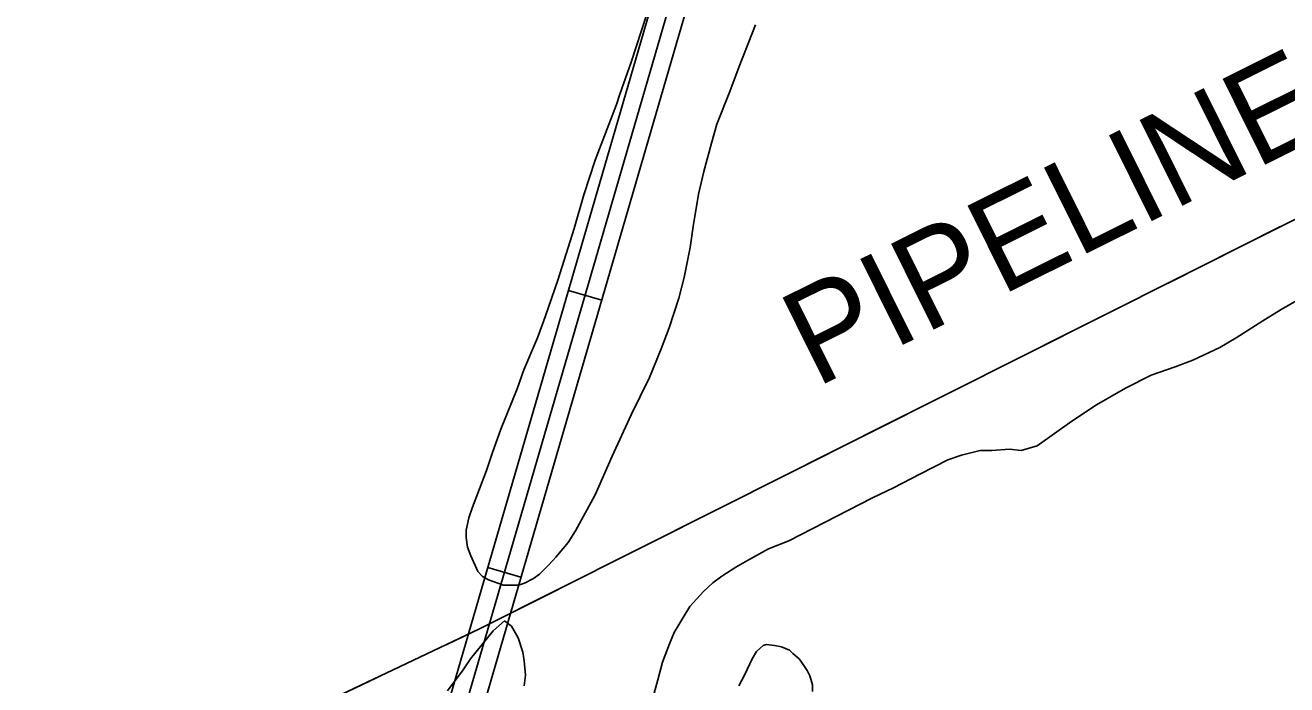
# Model space of a CAD drawing. Extents: x 3567028 to 3605064, y 510945 to 536587.
# Drawn here: x 3592975 to 3594068, y 517478 to 518049 of the extents above; entities that cross this region are included whole.
import ezdxf

# ---------------------------------------------------------------- set-up
doc = ezdxf.new("R2010")
doc.units = 0
for name, color, linetype in [('V-ROAD-CNTR', 7, 'Continuous'), ('V-SITE-VEGE', 7, 'Continuous'), ('V-UTIL-IDEN', 7, 'Continuous'), ('V-UTIL-LINE', 7, 'Continuous')]:
    doc.layers.add(name, color=color, linetype=linetype)

msp = doc.modelspace()

# ---------------------------------------------------------------- linework, layer by layer
at = {"layer": 'V-ROAD-CNTR'}
for p, q in [((3593446.1, 517819.3), (3593474.9, 517810.9)), ((3593376.1, 517579.3), (3593404.9, 517570.9))]:
    msp.add_line(p, q, dxfattribs=at)
for points in [[(3593075.5, 516536.6), (3593279.2, 517246.5), (3593647.5, 518510.8), (3593973.3, 519612.8), (3594189.4, 520289.5), (3594236.4, 520485.4), (3594284.3, 520636.9), (3594416.6, 521086), (3594537.9, 521497.5)], [(3594552.2, 521493.2), (3594431, 521081.8), (3594298.6, 520632.5), (3594250.9, 520481.3), (3594203.9, 520285.4), (3593987.6, 519608.4), (3593661.9, 518506.6), (3593293.6, 517242.3), (3593091.2, 516536.7)], [(3593106.8, 516536.8), (3593308, 517238.2), (3593676.3, 518502.4), (3594001.9, 519604), (3594218.3, 520281.4), (3594265.3, 520477.3), (3594313, 520628.1), (3594342.1, 520727.2)]]:
    msp.add_lwpolyline(points, dxfattribs=at)
at = {"layer": 'V-SITE-VEGE'}
for p, q in [((3594063.5, 517802.9), (3594085.2, 517815.2)), ((3594047.6, 517792.9), (3594063.5, 517802.9)), ((3594024.7, 517778.2), (3594047.6, 517792.9)), ((3593987, 517758.8), (3594010.5, 517770)), ((3594010.5, 517770), (3594024.7, 517778.2)), ((3593971.7, 517753), (3593987, 517758.8)), ((3593951.1, 517745.9), (3593971.7, 517753)), ((3593928.8, 517734.7), (3593951.1, 517745.9)), ((3593903.5, 517720.1), (3593928.8, 517734.7)), ((3593882.3, 517706), (3593903.5, 517720.1)), ((3593852.3, 517684.8), (3593882.3, 517706)), ((3593812.9, 517680.7), (3593828.2, 517681.9)), ((3593828.2, 517681.9), (3593838.2, 517680.7)), ((3593838.2, 517680.7), (3593852.3, 517684.8)), ((3593763, 517666.6), (3593774.7, 517672.5)), ((3593774.7, 517672.5), (3593786.5, 517676.6)), ((3593786.5, 517676.6), (3593802.9, 517680.7)), ((3593802.9, 517680.7), (3593812.9, 517680.7)), ((3593727.7, 517648.4), (3593750.6, 517660.1)), ((3593750.6, 517660.1), (3593763, 517666.6)), ((3593709.4, 517639.6), (3593727.7, 517648.4)), ((3593637.1, 517602.6), (3593709.4, 517639.6)), ((3593601.2, 517585.5), (3593619.5, 517595.5)), ((3593619.5, 517595.5), (3593637.1, 517602.6)), ((3593591.2, 517579.6), (3593601.2, 517585.5)), ((3593571.2, 517566.1), (3593578.9, 517572)), ((3593578.9, 517572), (3593591.2, 517579.6)), ((3593563, 517558.5), (3593571.2, 517566.1)), ((3593551.2, 517545.6), (3593563, 517558.5)), ((3593545.4, 517536.2), (3593551.2, 517545.6)), ((3593380.7, 517524.5), (3593390.7, 517533.3)), ((3593390.7, 517533.3), (3593396.6, 517528.6)), ((3593396.6, 517528.6), (3593402.5, 517518.6)), ((3593537.7, 517523.2), (3593545.4, 517536.2)), ((3593361.3, 517500.4), (3593380.7, 517524.5)), ((3593402.5, 517518.6), (3593406.6, 517506.2)), ((3593533.6, 517513.2), (3593537.7, 517523.2)), ((3593406.6, 517506.2), (3593407.8, 517498.6)), ((3593527.7, 517497.4), (3593533.6, 517513.2)), ((3593608.9, 517506.7), (3593605.3, 517500.3)), ((3593614.7, 517512), (3593608.9, 517506.7)), ((3593617.7, 517512.6), (3593614.7, 517512)), ((3593624.7, 517512), (3593617.7, 517512.6)), ((3593630.6, 517510.8), (3593624.7, 517512)), ((3593637.7, 517507.9), (3593630.6, 517510.8)), ((3593640.6, 517505), (3593637.7, 517507.9)), ((3593354.8, 517490.9), (3593361.3, 517500.4)), ((3593407.8, 517498.6), (3593408.9, 517486.2)), ((3593523.6, 517482.1), (3593527.7, 517497.4)), ((3593605.3, 517500.3), (3593598.8, 517486.7)), ((3593645.9, 517500.2), (3593640.6, 517505)), ((3593649.4, 517495.5), (3593645.9, 517500.2)), ((3593652.9, 517490.2), (3593649.4, 517495.5)), ((3593341.3, 517472.7), (3593354.8, 517490.9)), ((3593408.9, 517486.2), (3593407.7, 517476.8)), ((3593598.8, 517486.7), (3593593.6, 517476.8)), ((3593655.3, 517485.5), (3593652.9, 517490.2)), ((3593657.6, 517477.9), (3593655.3, 517485.5)), ((3593519.5, 517467.4), (3593523.6, 517482.1)), ((3593657.6, 517472), (3593657.6, 517477.9))]:
    msp.add_line(p, q, dxfattribs=at)
msp.add_lwpolyline([(3593608.1, 518049.1), (3593594, 518013.2), (3593585.8, 517991.5), (3593574.6, 517963.3), (3593569.9, 517946.8), (3593563.4, 517922.1), (3593558.7, 517902.7), (3593554, 517874.5), (3593551.6, 517856.3), (3593546.3, 517830.4), (3593541.6, 517812.7), (3593533.4, 517786.9), (3593526.3, 517768.7), (3593516.3, 517744), (3593508.1, 517727.5), (3593500.4, 517711.6), (3593483.9, 517675.8), (3593469.2, 517642.3), (3593452.2, 517611.1), (3593445.7, 517601.1), (3593435.1, 517588.2), (3593429.2, 517581.7), (3593421, 517573.5), (3593415.7, 517570), (3593408.1, 517565.8), (3593402.8, 517564.1), (3593389.8, 517564.1), (3593376.9, 517568.8), (3593371.6, 517571.7), (3593367.5, 517575.9), (3593361.6, 517589.4), (3593358.7, 517597), (3593357.5, 517605.3), (3593357.5, 517611.7), (3593359.9, 517622.3), (3593362.8, 517631.7), (3593375.2, 517663.5), (3593379.9, 517678.2), (3593387.5, 517699.3), (3593401.6, 517734), (3593407.5, 517750.5), (3593419.3, 517778.1), (3593425.8, 517796.3), (3593437, 517828.1), (3593444, 517851), (3593451.1, 517872.8), (3593459.3, 517902.1), (3593469.3, 517932.1), (3593487.6, 517980.3), (3593490.5, 517989.2), (3593500.5, 518016.8), (3593514.1, 518058.5)], dxfattribs=at)
at = {"layer": 'V-UTIL-LINE'}
for points in [[(3592391.9, 517062.8), (3593369.1, 517526.2), (3594582.6, 518135.5), (3595477.2, 518582.3), (3595939.8, 518818.4), (3596329.9, 519070.3), (3597241.4, 518623.6), (3597895.1, 518235.1), (3598852.4, 517733.3), (3599147.3, 517541.9), (3599253.9, 517354.5)], [(3593965.6, 517825.7), (3594062.4, 517874.3)], [(3593809.3, 517747.3), (3593906.1, 517795.9)], [(3593653, 517668.8), (3593749.8, 517717.4)], [(3593496.7, 517590.3), (3593593.5, 517638.9)], [(3593340.1, 517512.5), (3593369.1, 517526.2), (3593437.2, 517560.4)], [(3593182.1, 517437.5), (3593279.9, 517483.9)]]:
    msp.add_lwpolyline(points, dxfattribs=at)

# ---------------------------------------------------------------- texts
at = {"layer": 'V-UTIL-IDEN'}
msp.add_text('PIPELINE', height=83, rotation=26.4397, dxfattribs=at).set_placement((3593660.5, 517734.6))

doc.saveas('drawing.dxf')
